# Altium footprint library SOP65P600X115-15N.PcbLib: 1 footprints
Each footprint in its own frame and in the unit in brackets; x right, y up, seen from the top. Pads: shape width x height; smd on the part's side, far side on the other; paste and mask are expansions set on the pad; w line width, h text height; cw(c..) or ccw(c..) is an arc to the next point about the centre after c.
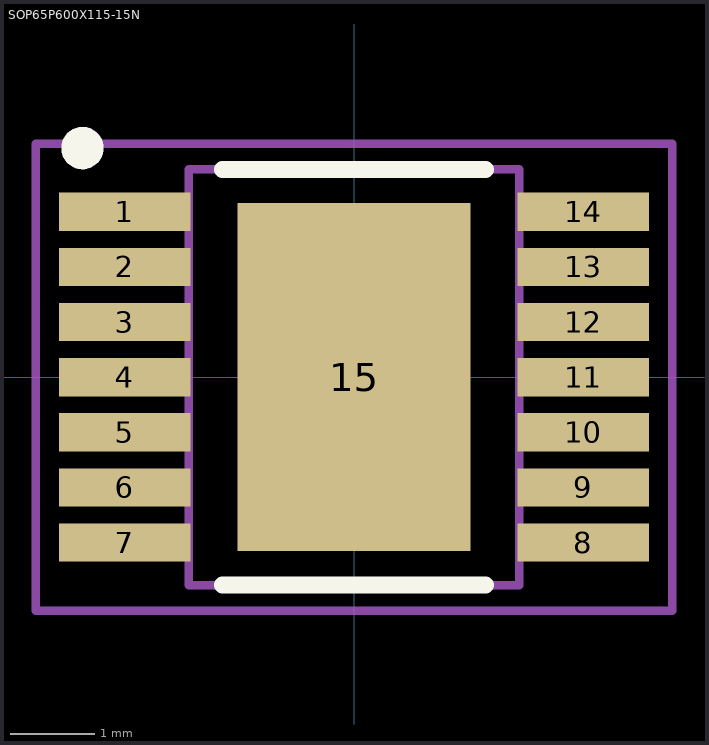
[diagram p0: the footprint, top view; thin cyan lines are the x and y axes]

## SOP65P600X115-15N [mm] "SOP,0.65mm pitch;14 pin,3.90mm W X 4.90mm L X 1.15mm H body (w/thermal tab)"
height 1.15
pads (15):
  rect 1.55x0.45 smd paste+0 mask+0: 1(-2.7,1.95) 2(-2.7,1.3) 3(-2.7,0.65) 4(-2.7,0) 5(-2.7,-0.65) 6(-2.7,-1.3) 7(-2.7,-1.95) 8(2.7,-1.95) 9(2.7,-1.3) 10(2.7,-0.65) 11(2.7,0) 12(2.7,0.65) 13(2.7,1.3) 14(2.7,1.95)
  rect 2.75x4.1 smd paste+0 mask+0: 15(0,0)
Top Overlay:
  circle w0.25: c-3.2,2.7 r0.125
  lines w0.2: -1.55,-2.45 1.55,-2.45 ; -1.55,2.45 1.55,2.45
M3 (ASY_Text_Top):
  text ".DESIGNATOR" at 0,0 h1.2
M13 (CMP_Body_OTL_Top):
  lines w0.1: -1.95,-2.45 -1.95,2.45 1.95,2.45 1.95,-2.45 -1.95,-2.45
M15 (CMP_Courtyard_Top):
  lines w0.1: -0.5,0 0.5,0 ; 0,-0.5 0,0.5 ; -3.75,-2.75 -3.75,2.75 3.75,2.75 3.75,-2.75 -3.75,-2.75
3D body "TSDSO-14.stp": height 1.16, standoff 0, extent -3,-2.45 3,2.45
